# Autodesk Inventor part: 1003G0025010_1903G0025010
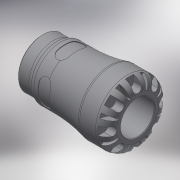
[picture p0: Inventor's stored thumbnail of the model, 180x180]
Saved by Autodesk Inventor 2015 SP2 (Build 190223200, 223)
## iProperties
Created: 2016-12
Part Number: 1003G0025010_1903G0025010
Material: Generic
Description: PLASSON FEMALE ADAPTOR 25X1" SERIES 1
Document SubType Name: Modeling
Designer: KIM
Mass: 664.223 g
Surface Area: 733.008 cm^2
Volume: 474.445 cm^3
Density: 1 g/cm^3
Appearance: Default
Author: KIM
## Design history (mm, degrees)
derived "1003G.ipt"
feature "Solid1::1003G.ipt"
tag "TaggingFeature1"
body "Solid1"
other parameters: "d1" = 20.16, "d2" = 25, "d3" = 31.25, "d4" = 47, "d6" = 48, "d8" = 39.95, "d13" = 6.3, "d14" = 6.3, "d15" = 0, "d17" = 360 deg, "d19" = 8 deg, "d20" = 0.5, "d21" = 0.5, "d22" = 8 deg, "d24" = 0, "d26" = 360 deg, "d32" = 4.7, "d33" = 4.7, "d39" = 0.90873, "d42" = 30.291, "d43" = 36.66, "d46" = 2.08333, "d47" = 13.5, "d48" = 28.77645, "d50" = 6.105, "d51" = 0.47, "d54" = 8.75, "d55" = 5.5, "d57" = 12.348, "d58" = 0, "d68" = 360 deg, "d72" = 0.5, "d74" = 0, "d76" = 7.4375, "d_" = 25, "E_" = 47, "l_" = 48, "G_" = 30.291, "l_2" = 13.5, "d9" = 7.875, "d11" = 47, "d12" = 31.25, "d49" = 18.5
